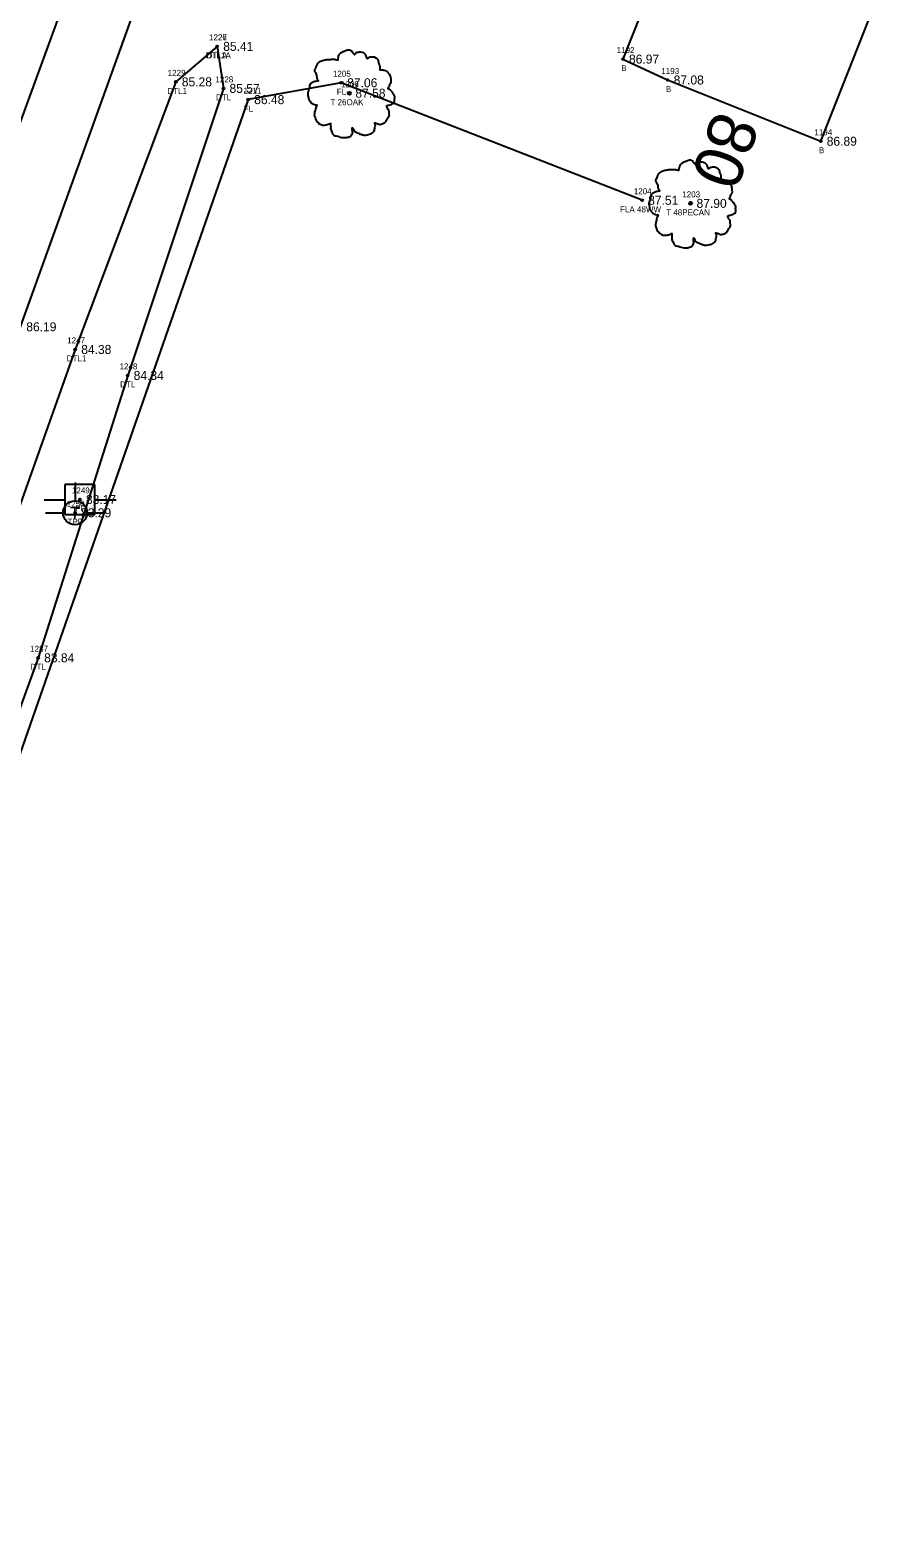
# Model space of a CAD drawing. Extents: x 2139392 to 2143384, y 505395 to 510520.
# Drawn here: x 2141327.7 to 2141467.9, y 509825.4 to 510076.4 of the extents above; entities that cross this region are included whole.
import ezdxf

# ---------------------------------------------------------------- set-up
doc = ezdxf.new("R2010")
doc.units = 0
for name, color, linetype in [('RD_EX_Bldg', 7, 'Continuous'), ('RD_EX_Bldg_txCode', 7, 'Continuous'), ('RD_EX_Fence_Other', 7, 'Continuous'), ('RD_EX_Fence_Other_txCode', 7, 'Continuous'), ('RD_EX_H2O', 7, 'Continuous'), ('RD_EX_H2O_txCode', 7, 'Continuous'), ('RD_EX_Road', 7, 'Continuous'), ('RD_EX_TX_Bldg_ELEV', 7, 'Continuous'), ('RD_EX_TX_Fence_Other_ELEV', 7, 'Continuous'), ('RD_EX_TX_H2O_ELEV', 7, 'Continuous'), ('RD_EX_TX_Road_ELEV', 7, 'Continuous'), ('RD_EX_TX_UT_ELEV', 7, 'Continuous'), ('RD_EX_TX_VEG_ELEV', 7, 'Continuous'), ('RD_EX_UT', 7, 'Continuous'), ('RD_EX_UT_txCode', 7, 'Continuous'), ('RD_EX_VEG', 7, 'Continuous'), ('RD_EX_VEG_txCode', 7, 'Continuous'), ('RD_HC_Cl', 7, 'Continuous'), ('RD_HC_Survey_ELEV', 7, 'Continuous'), ('RD_HC_TX_Sta50', 7, 'Continuous'), ('RD_SMD_Locator', 7, 'Continuous')]:
    doc.layers.add(name, color=color, linetype=linetype)

msp = doc.modelspace()

# ---------------------------------------------------------------- linework, layer by layer
at = {"layer": 'RD_EX_Bldg'}
msp.add_lwpolyline([(2141451.72, 510113.31), (2141444.82, 510096.53), (2141437.1, 510098.65), (2141426.42, 510071.61), (2141433.86, 510068.13), (2141459.35, 510057.93), (2141477.25, 510103.22), (2141451.72, 510113.31)], dxfattribs=at)
at = {"layer": 'RD_EX_Fence_Other'}
msp.add_lwpolyline([(2141429.61, 510048.1), (2141379.49, 510067.67), (2141364, 510064.86), (2141272.95, 509804.04), (2141395.5, 509766.95)], dxfattribs=at)
at = {"layer": 'RD_EX_H2O'}
for points in [[(2141358.84, 510073.73), (2141351.95, 510067.82), (2141335.19, 510023.26), (2141318.11, 509975.22), (2141278.81, 509873.19), (2141249.28, 509788.39)], [(2141358.84, 510073.73), (2141359.89, 510066.73), (2141343.93, 510018.93), (2141329.02, 509971.91), (2141291.47, 509868.4), (2141257.4, 509785.24), (2141249.28, 509788.39)]]:
    msp.add_lwpolyline(points, dxfattribs=at)
at = {"layer": 'RD_EX_Road'}
msp.add_lwpolyline([(2141412.62, 510288.46), (2141398.29, 510238.16), (2141381.65, 510185.39), (2141379.05, 510176.51), (2141367.08, 510141.57), (2141363.58, 510131.95), (2141345.23, 510080.36), (2141326.05, 510027.03), (2141308.64, 509979.4), (2141271.24, 509876.37), (2141240, 509789.51), (2141233.78, 509773.43), (2141223.56, 509746.41), (2141212.18, 509714.93), (2141204.36, 509694.36), (2141197.99, 509676.56), (2141193.66, 509664.6), (2141161.61, 509577.24), (2141123.75, 509473.61), (2141115.5, 509450.65), (2141102.09, 509414.61), (2141086.27, 509371.27), (2141050.42, 509272.83)], dxfattribs=at)
at = {"layer": 'RD_EX_UT'}
for p, q in [((2141335.17, 510001.13), (2141335.17, 509998.06)), ((2141338.47, 510000.79), (2141333.47, 510000.79)), ((2141333.47, 510000.79), (2141333.47, 509995.79)), ((2141338.47, 509995.79), (2141338.47, 510000.79)), ((2141330.04, 509998.23), (2141333.51, 509998.23)), ((2141338.4, 509998.23), (2141342.04, 509998.23)), ((2141330.23, 509996.07), (2141333.17, 509996.07)), ((2141333.47, 509995.79), (2141338.47, 509995.79)), ((2141337.17, 509996.07), (2141340.23, 509996.07))]:
    msp.add_line(p, q, dxfattribs=at)
msp.add_circle((2141335.17, 509996.06), 2, dxfattribs=at)
at = {"layer": 'RD_EX_VEG'}
for centre, radius in [((2141380.85, 510065.93), 0.25), ((2141380.84, 510065.91), 0.0001), ((2141437.67, 510047.58), 0.25), ((2141437.66, 510047.56), 0.0001)]:
    msp.add_circle(centre, radius, dxfattribs=at)
for points in [[(2141380.99, 510073.09), (2141380.69, 510073.12), (2141380.36, 510073.02), (2141380.11, 510072.92), (2141379.89, 510072.84), (2141379.66, 510072.74), (2141379.36, 510072.57), (2141379.14, 510072.37), (2141379.01, 510072.12), (2141378.96, 510071.89), (2141378.91, 510071.62), (2141378.91, 510071.44), (2141378.79, 510071.42), (2141378.64, 510071.44), (2141378.39, 510071.52), (2141378.14, 510071.52), (2141377.89, 510071.52), (2141377.54, 510071.49), (2141377.19, 510071.49), (2141376.91, 510071.44), (2141376.59, 510071.39), (2141376.21, 510071.27), (2141375.86, 510071.14), (2141375.56, 510070.89), (2141375.31, 510070.42), (2141375.19, 510070.07), (2141375.04, 510069.82), (2141375.19, 510069.37), (2141375.36, 510069.02), (2141375.39, 510068.82), (2141375.46, 510068.4), (2141375.56, 510068.17), (2141375.69, 510067.97), (2141375.61, 510067.95), (2141375.24, 510067.9), (2141374.94, 510067.8), (2141374.51, 510067.57), (2141374.29, 510067.35), (2141374.19, 510067.02), (2141374.16, 510066.67), (2141374.06, 510066.47), (2141373.99, 510066.2), (2141373.96, 510066.12), (2141373.91, 510065.8), (2141374.01, 510065.35), (2141374.04, 510065), (2141374.16, 510064.77), (2141374.31, 510064.6), (2141374.49, 510064.35), (2141374.89, 510064.12), (2141375.21, 510064.02), (2141375.41, 510064), (2141375.24, 510063.5), (2141375.19, 510063.15), (2141375.06, 510062.75), (2141375.06, 510062.67), (2141375.01, 510062.2), (2141375.16, 510061.87), (2141375.24, 510061.5), (2141375.41, 510061.27), (2141375.69, 510060.97), (2141376.01, 510060.75), (2141376.51, 510060.62), (2141376.91, 510060.65), (2141377.49, 510060.82), (2141377.74, 510060.9), (2141377.71, 510060.72), (2141377.74, 510060.35), (2141377.74, 510059.92), (2141377.89, 510059.6), (2141377.99, 510059.32), (2141378.14, 510059.07), (2141378.46, 510058.85), (2141378.86, 510058.78), (2141379.29, 510058.63), (2141379.74, 510058.55), (2141380.24, 510058.53), (2141380.84, 510058.68), (2141381.11, 510058.8), (2141381.21, 510058.97), (2141381.41, 510059.35), (2141381.36, 510059.57), (2141381.39, 510060.17), (2141381.49, 510060), (2141381.66, 510059.65), (2141382.16, 510059.35), (2141382.56, 510059.17), (2141383.04, 510059.02), (2141383.34, 510058.95), (2141383.81, 510059.02), (2141384.19, 510059.1), (2141384.56, 510059.22), (2141384.86, 510059.5), (2141385.03, 510059.77), (2141385.08, 510060.05), (2141385.16, 510060.42), (2141385.21, 510060.6)], [(2141385.21, 510060.6), (2141385.13, 510060.77), (2141385.08, 510061.02), (2141385.16, 510061), (2141385.33, 510060.95), (2141385.61, 510060.82), (2141385.83, 510060.75), (2141386.16, 510060.77), (2141386.43, 510060.87), (2141386.88, 510061.15), (2141387.16, 510061.62), (2141387.43, 510062.02), (2141387.51, 510062.35), (2141387.46, 510062.57), (2141387.43, 510063.07), (2141387.23, 510063.32), (2141387.18, 510063.45), (2141387.08, 510063.85), (2141387.16, 510063.9), (2141387.43, 510063.95), (2141387.81, 510064.07), (2141388.08, 510064.2), (2141388.31, 510064.37), (2141388.38, 510064.6), (2141388.36, 510065), (2141388.41, 510065.4), (2141388.33, 510065.55), (2141388.23, 510065.7), (2141388.16, 510065.9), (2141388.01, 510066.05), (2141387.91, 510066.2), (2141387.81, 510066.3), (2141387.68, 510066.45), (2141387.51, 510066.57), (2141387.36, 510066.62), (2141387.31, 510066.77), (2141387.46, 510066.97), (2141387.51, 510067.07), (2141387.53, 510067.3), (2141387.76, 510067.65), (2141387.81, 510068.05), (2141387.76, 510068.47), (2141387.71, 510068.75), (2141387.56, 510069.02), (2141387.36, 510069.27), (2141387.23, 510069.45), (2141387.06, 510069.57), (2141386.73, 510069.7), (2141386.48, 510069.75), (2141386.13, 510069.75), (2141385.93, 510069.8), (2141385.96, 510069.85), (2141385.96, 510070), (2141385.96, 510070.27), (2141385.88, 510070.72), (2141385.73, 510071.22), (2141385.73, 510071.24), (2141385.63, 510071.49), (2141385.41, 510071.69), (2141385.23, 510071.79), (2141385.03, 510071.92), (2141384.78, 510071.94), (2141384.48, 510071.94), (2141384.21, 510071.89), (2141384.01, 510071.79), (2141383.84, 510071.67), (2141383.76, 510071.82), (2141383.66, 510072.12), (2141383.61, 510072.27), (2141383.46, 510072.44), (2141383.24, 510072.64), (2141382.79, 510072.77), (2141382.16, 510072.69), (2141381.86, 510072.49), (2141381.71, 510072.32), (2141381.66, 510072.44), (2141381.46, 510072.64), (2141381.36, 510072.82), (2141381.19, 510072.94), (2141381.04, 510073.04), (2141380.94, 510073.09)], [(2141437.81, 510054.75), (2141437.51, 510054.77), (2141437.18, 510054.67), (2141436.93, 510054.57), (2141436.71, 510054.5), (2141436.48, 510054.4), (2141436.18, 510054.22), (2141435.96, 510054.02), (2141435.83, 510053.77), (2141435.78, 510053.55), (2141435.73, 510053.27), (2141435.73, 510053.1), (2141435.61, 510053.07), (2141435.46, 510053.1), (2141435.21, 510053.17), (2141434.96, 510053.17), (2141434.71, 510053.17), (2141434.36, 510053.15), (2141434.01, 510053.15), (2141433.73, 510053.1), (2141433.41, 510053.05), (2141433.03, 510052.92), (2141432.68, 510052.8), (2141432.38, 510052.55), (2141432.13, 510052.07), (2141432.01, 510051.72), (2141431.86, 510051.47), (2141432.01, 510051.02), (2141432.18, 510050.67), (2141432.21, 510050.47), (2141432.28, 510050.05), (2141432.38, 510049.82), (2141432.51, 510049.62), (2141432.43, 510049.6), (2141432.06, 510049.55), (2141431.76, 510049.45), (2141431.33, 510049.22), (2141431.11, 510049), (2141431.01, 510048.67), (2141430.98, 510048.32), (2141430.88, 510048.12), (2141430.81, 510047.85), (2141430.78, 510047.77), (2141430.73, 510047.45), (2141430.83, 510047), (2141430.86, 510046.65), (2141430.98, 510046.42), (2141431.13, 510046.25), (2141431.31, 510046), (2141431.71, 510045.78), (2141432.03, 510045.68), (2141432.23, 510045.65), (2141432.06, 510045.15), (2141432.01, 510044.8), (2141431.88, 510044.4), (2141431.88, 510044.33), (2141431.83, 510043.85), (2141431.98, 510043.53), (2141432.06, 510043.15), (2141432.23, 510042.93), (2141432.51, 510042.63), (2141432.83, 510042.4), (2141433.33, 510042.28), (2141433.73, 510042.3), (2141434.31, 510042.48), (2141434.56, 510042.55), (2141434.53, 510042.38), (2141434.56, 510042), (2141434.56, 510041.58), (2141434.71, 510041.25), (2141434.81, 510040.98), (2141434.96, 510040.73), (2141435.28, 510040.5), (2141435.68, 510040.43), (2141436.11, 510040.28), (2141436.56, 510040.2), (2141437.06, 510040.18), (2141437.66, 510040.33), (2141437.93, 510040.45), (2141438.03, 510040.63), (2141438.23, 510041), (2141438.18, 510041.23), (2141438.21, 510041.83), (2141438.31, 510041.65), (2141438.48, 510041.3), (2141438.98, 510041), (2141439.38, 510040.83), (2141439.86, 510040.68), (2141440.16, 510040.6), (2141440.63, 510040.68), (2141441.01, 510040.75), (2141441.38, 510040.88), (2141441.68, 510041.15), (2141441.86, 510041.43), (2141441.91, 510041.7), (2141441.98, 510042.08), (2141442.03, 510042.25)], [(2141442.03, 510042.25), (2141441.96, 510042.43), (2141441.91, 510042.68), (2141441.98, 510042.65), (2141442.15, 510042.6), (2141442.43, 510042.48), (2141442.65, 510042.4), (2141442.98, 510042.43), (2141443.25, 510042.53), (2141443.7, 510042.8), (2141443.98, 510043.28), (2141444.25, 510043.68), (2141444.33, 510044), (2141444.28, 510044.23), (2141444.25, 510044.73), (2141444.05, 510044.98), (2141444, 510045.1), (2141443.9, 510045.5), (2141443.98, 510045.55), (2141444.25, 510045.6), (2141444.63, 510045.73), (2141444.9, 510045.85), (2141445.13, 510046.03), (2141445.2, 510046.25), (2141445.18, 510046.65), (2141445.23, 510047.05), (2141445.15, 510047.2), (2141445.05, 510047.35), (2141444.98, 510047.55), (2141444.83, 510047.7), (2141444.73, 510047.85), (2141444.63, 510047.95), (2141444.5, 510048.1), (2141444.33, 510048.22), (2141444.18, 510048.27), (2141444.13, 510048.42), (2141444.28, 510048.62), (2141444.33, 510048.72), (2141444.35, 510048.95), (2141444.58, 510049.3), (2141444.63, 510049.7), (2141444.58, 510050.12), (2141444.53, 510050.4), (2141444.38, 510050.67), (2141444.18, 510050.92), (2141444.05, 510051.1), (2141443.88, 510051.22), (2141443.55, 510051.35), (2141443.3, 510051.4), (2141442.95, 510051.4), (2141442.75, 510051.45), (2141442.78, 510051.5), (2141442.78, 510051.65), (2141442.78, 510051.92), (2141442.7, 510052.37), (2141442.55, 510052.87), (2141442.55, 510052.9), (2141442.45, 510053.15), (2141442.23, 510053.35), (2141442.05, 510053.45), (2141441.86, 510053.57), (2141441.61, 510053.6), (2141441.31, 510053.6), (2141441.03, 510053.55), (2141440.83, 510053.45), (2141440.66, 510053.32), (2141440.58, 510053.47), (2141440.48, 510053.77), (2141440.43, 510053.92), (2141440.28, 510054.1), (2141440.06, 510054.3), (2141439.61, 510054.42), (2141438.98, 510054.35), (2141438.68, 510054.15), (2141438.53, 510053.97), (2141438.48, 510054.1), (2141438.28, 510054.3), (2141438.18, 510054.47), (2141438.01, 510054.6), (2141437.86, 510054.7), (2141437.76, 510054.75)]]:
    msp.add_spline(points, degree=3, dxfattribs=at)
at = {"layer": 'RD_HC_Cl'}
msp.add_line((2141333.53, 510081.69), (2140670.51, 508268.37), dxfattribs=at)
at = {"layer": 'RD_SMD_Locator'}
for centre in [(2141358.84, 510073.73), (2141358.84, 510073.73), (2141426.42, 510071.61), (2141351.95, 510067.82), (2141359.89, 510066.73), (2141379.49, 510067.67), (2141433.86, 510068.13), (2141364, 510064.86), (2141380.85, 510065.93), (2141459.35, 510057.93), (2141429.61, 510048.1), (2141437.67, 510047.58), (2141335.19, 510023.26), (2141343.93, 510018.93), (2141335.17, 509996.06), (2141335.98, 509998.28), (2141329.02, 509971.91)]:
    msp.add_circle(centre, 0.15, dxfattribs=at)

# ---------------------------------------------------------------- texts
at = {"layer": 'RD_EX_Bldg_txCode'}
for s, p in [('1192', (2141425.36, 510072.61)), ('B', (2141426.12, 510069.61)), ('1193', (2141432.8, 510069.13)), ('B', (2141433.56, 510066.13)), ('1194', (2141458.29, 510058.93)), ('B', (2141459.04, 510055.93))]:
    msp.add_text(s, height=1, dxfattribs=at).set_placement(p)
at = {"layer": 'RD_EX_Fence_Other_txCode'}
for s, p in [('1205', (2141378.11, 510068.67)), ('1211', (2141363.22, 510065.86)), ('FL', (2141378.76, 510065.67)), ('FL', (2141363.27, 510062.86)), ('1204', (2141428.22, 510049.1)), ('FLA 48WW', (2141425.93, 510046.1))]:
    msp.add_text(s, height=1, dxfattribs=at).set_placement(p)
at = {"layer": 'RD_EX_H2O_txCode'}
for s, p in [('1226', (2141357.47, 510074.73)), ('1227', (2141357.49, 510074.73)), ('DTL1A', (2141356.94, 510071.73)), ('DTLA', (2141357.1, 510071.73)), ('1229', (2141350.6, 510068.82)), ('DTL1', (2141350.54, 510065.82)), ('1228', (2141358.54, 510067.73)), ('DTL', (2141358.64, 510064.73)), ('1247', (2141333.85, 510024.26)), ('DTL1', (2141333.78, 510021.26)), ('1248', (2141342.58, 510019.93)), ('DTL', (2141342.68, 510016.93)), ('1287', (2141327.68, 509972.91)), ('DTL', (2141327.78, 509969.91))]:
    msp.add_text(s, height=1, dxfattribs=at).set_placement(p)
at = {"layer": 'RD_EX_TX_Bldg_ELEV'}
for s, p in [('86.97', (2141427.42, 510070.86)), ('87.08', (2141434.86, 510067.38)), ('86.89', (2141460.35, 510057.18))]:
    msp.add_text(s, height=1.5, dxfattribs=at).set_placement(p)
at = {"layer": 'RD_EX_TX_Fence_Other_ELEV'}
for s, p in [('87.06', (2141380.49, 510066.92)), ('86.48', (2141365, 510064.11)), ('87.51', (2141430.61, 510047.35))]:
    msp.add_text(s, height=1.5, dxfattribs=at).set_placement(p)
at = {"layer": 'RD_EX_TX_H2O_ELEV'}
for s, p in [('85.41', (2141359.84, 510072.98)), ('85.41', (2141359.84, 510072.98)), ('85.28', (2141352.95, 510067.07)), ('85.57', (2141360.89, 510065.98)), ('84.38', (2141336.19, 510022.51)), ('84.34', (2141344.93, 510018.18)), ('83.84', (2141330.02, 509971.16))]:
    msp.add_text(s, height=1.5, dxfattribs=at).set_placement(p)
at = {"layer": 'RD_EX_TX_Road_ELEV'}
msp.add_text('86.19', height=1.5, dxfattribs=at).set_placement((2141327.05, 510026.28))
at = {"layer": 'RD_EX_TX_UT_ELEV'}
msp.add_text('83.29', height=1.5, dxfattribs=at).set_placement((2141336.17, 509995.31))
at = {"layer": 'RD_EX_TX_VEG_ELEV'}
for s, p in [('87.58', (2141381.85, 510065.18)), ('87.90', (2141438.67, 510046.83))]:
    msp.add_text(s, height=1.5, dxfattribs=at).set_placement(p)
at = {"layer": 'RD_EX_UT'}
msp.add_text('T', height=2, dxfattribs=at).set_placement((2141334.32, 509995.01))
at = {"layer": 'RD_EX_UT_txCode'}
for s, p in [('1249', (2141334.63, 509999.28)), ('1250', (2141333.78, 509997.06)), ('PP', (2141335.2, 509996.28)), ('TPP', (2141333.9, 509994.06))]:
    msp.add_text(s, height=1, dxfattribs=at).set_placement(p)
at = {"layer": 'RD_EX_VEG_txCode'}
for s, p in [('1206', (2141379.45, 510066.93)), ('T 26OAK', (2141377.7, 510063.93)), ('1203', (2141436.29, 510048.58)), ('T 48PECAN', (2141433.61, 510045.58))]:
    msp.add_text(s, height=1, dxfattribs=at).set_placement(p)
at = {"layer": 'RD_HC_Survey_ELEV'}
msp.add_text('83.17', height=1.5, dxfattribs=at).set_placement((2141336.98, 509997.53))
at = {"layer": 'RD_HC_TX_Sta50'}
msp.add_text('80', height=8, rotation=250.1875, dxfattribs=at).set_placement((2141441.74, 510063.31))

doc.saveas('drawing.dxf')
